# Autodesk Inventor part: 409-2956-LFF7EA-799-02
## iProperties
Created: 2010-11
Part Number: 409-2956-LFF7EA-799-02
Material: 3/4" OD TUBE - SS
Document SubType Name: Modeling
Designer: S. Boerckel
Engineer: Steve Boerckel
Mass: 309.983 g
Surface Area: 466.545 cm^2
Volume: 38.3643 cm^3
Density: 8.08 g/cm^3
Description: DRAIN TUBING
Length: 22.316 in
Author: S. Boerckel
Revision Number: 0
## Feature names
1. Sweep1
